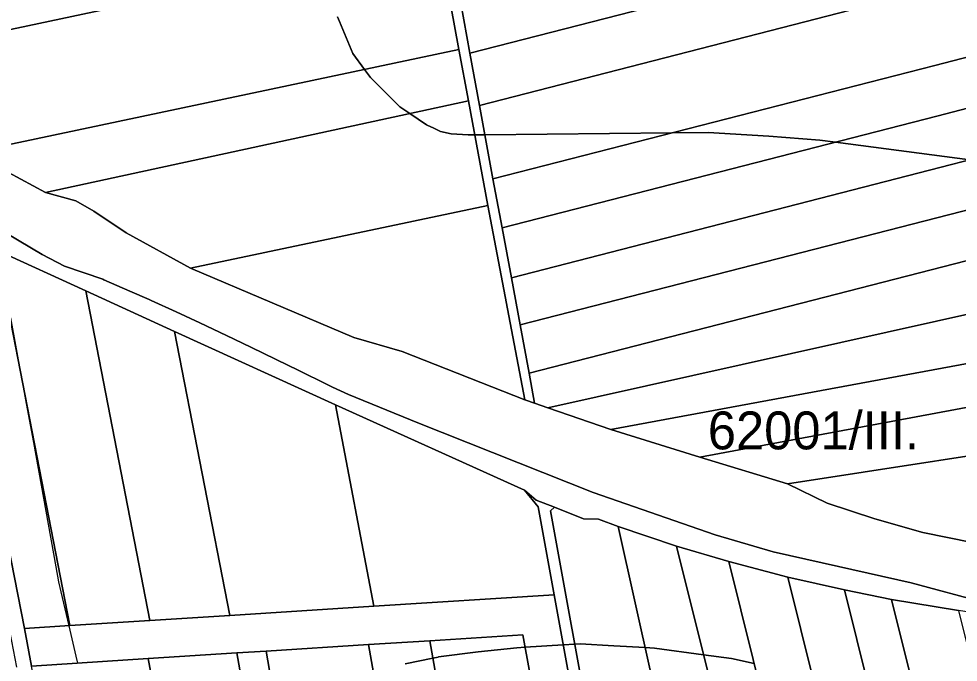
# Model space of a CAD drawing. Extents: x -521939 to -516426, y -1197857 to -1189551.
# Drawn here: x -519779.4 to -519407.3, y -1193004.4 to -1192749.7 of the extents above; entities that cross this region are included whole.
import ezdxf

# ---------------------------------------------------------------- set-up
doc = ezdxf.new("R2010")
doc.units = 0
for name, color, linetype in [('95560013', 7, 'Continuous'), ('95640013', 7, 'Continuous'), ('95660013', 7, 'Continuous')]:
    doc.layers.add(name, color=color, linetype=linetype)

msp = doc.modelspace()

# ---------------------------------------------------------------- linework, layer by layer
at = {"layer": '95560013'}
for points in [[(-519613.24, -1192717.85), (-519676.82, -1192731.35), (-519853.29, -1192768.82), (-519889.94, -1192741.9), (-519712.96, -1192704.38), (-519619.47, -1192684.56)], [(-519412.38, -1192694.25), (-519407.47, -1192713.71), (-519600.82, -1192763.32), (-519604.4, -1192743.51)], [(-519407.47, -1192713.71), (-519402.4, -1192733.96), (-519417.77, -1192737.92), (-519596.97, -1192784.09), (-519600.82, -1192763.32)], [(-519605.13, -1192761.84), (-519798.31, -1192802.61), (-519853.29, -1192768.82), (-519676.82, -1192731.35), (-519613.24, -1192717.85)], [(-519596.97, -1192784.09), (-519417.77, -1192737.92), (-519402.4, -1192733.96), (-519395.16, -1192762.71), (-519416.57, -1192768.19), (-519591.64, -1192813)], [(-519768.91, -1192818.48), (-519798.31, -1192802.61), (-519605.13, -1192761.84), (-519601.35, -1192782.23)], [(-519591.64, -1192813), (-519416.57, -1192768.19), (-519395.16, -1192762.71), (-519390.4, -1192781.7), (-519415.79, -1192788.23), (-519587.96, -1192832.51)], [(-519711.44, -1192848.38), (-519736.95, -1192834.43), (-519749.68, -1192825.91), (-519756.9, -1192821.72), (-519768.91, -1192818.48), (-519601.35, -1192782.23), (-519593.72, -1192823.59)], [(-519587.96, -1192832.51), (-519415.79, -1192788.23), (-519390.4, -1192781.7), (-519385.51, -1192801.11), (-519409.97, -1192807.4), (-519584.34, -1192852.24)], [(-519385.51, -1192801.11), (-519380.86, -1192819.59), (-519406.01, -1192826.04), (-519580.89, -1192870.89), (-519584.34, -1192852.24), (-519409.97, -1192807.4)], [(-519380.86, -1192819.59), (-519376.15, -1192838.32), (-519404.18, -1192845.51), (-519577.35, -1192889.93), (-519580.89, -1192870.89), (-519406.01, -1192826.04)], [(-519578.96, -1192900.47), (-519627.56, -1192881.34), (-519646.77, -1192875.82), (-519711.44, -1192848.38), (-519593.72, -1192823.59)], [(-519807.94, -1192834.96), (-519805.68, -1192833.36), (-519788.21, -1192841.3), (-519759.2, -1192989.89), (-519777.13, -1192991.04)], [(-519575.19, -1192901.81), (-519577.35, -1192889.93), (-519404.18, -1192845.51), (-519376.15, -1192838.32), (-519370.94, -1192859.31), (-519396.4, -1192864.98), (-519569.95, -1192903.63)], [(-519727.53, -1192987.89), (-519759.2, -1192989.89), (-519788.21, -1192841.3), (-519752.94, -1192857.37)], [(-519695.85, -1192985.85), (-519727.53, -1192987.89), (-519752.94, -1192857.37), (-519717.76, -1192873.41)], [(-519365.89, -1192879.09), (-519544.98, -1192912.28), (-519569.95, -1192903.63), (-519396.4, -1192864.98), (-519370.94, -1192859.31)], [(-519695.85, -1192985.85), (-519717.76, -1192873.41), (-519653.99, -1192902.46), (-519638.79, -1192982.16)], [(-519509.74, -1192923.15), (-519544.98, -1192912.28), (-519365.89, -1192879.09), (-519361.74, -1192895.7)], [(-519475.01, -1192933.77), (-519509.74, -1192923.15), (-519361.74, -1192895.7), (-519356.73, -1192915.59)], [(-519638.79, -1192982.16), (-519653.99, -1192902.46), (-519579.08, -1192936.23), (-519573.73, -1192942.87), (-519567.38, -1192977.66)], [(-519440.39, -1192947.55), (-519459.24, -1192941.4), (-519475.01, -1192933.77), (-519356.73, -1192915.59), (-519343.21, -1192969.49), (-519360.04, -1192967.68), (-519382.21, -1192963.28), (-519382, -1192962.28), (-519401.78, -1192957), (-519421.33, -1192953.08)], [(-519568.87, -1192944.42), (-519567.2, -1192943.06), (-519555.74, -1192947.57), (-519549.76, -1192947.78), (-519542.07, -1192950.61), (-519502.89, -1193125.92), (-519492.9, -1193170.62), (-519526.25, -1193178), (-519534.72, -1193131.58)], [(-519467.25, -1193165.07), (-519492.9, -1193170.62), (-519502.89, -1193125.92), (-519542.07, -1192950.61), (-519518.93, -1192958.37), (-519470.42, -1193152.39)], [(-519449.34, -1193161.11), (-519467.25, -1193165.07), (-519470.42, -1193152.39), (-519518.93, -1192958.37), (-519498.2, -1192964.55), (-519455.01, -1193138.3)], [(-519498.2, -1192964.55), (-519474.87, -1192970.68), (-519428.65, -1193156.57), (-519449.34, -1193161.11), (-519455.01, -1193138.3)], [(-519428.65, -1193156.57), (-519474.87, -1192970.68), (-519452.37, -1192975.76), (-519408.54, -1193152.16)], [(-519452.37, -1192975.76), (-519433.72, -1192979.51), (-519391.66, -1193148.43), (-519408.54, -1193152.16)], [(-519391.66, -1193148.43), (-519433.72, -1192979.51), (-519407.22, -1192983.93), (-519367.63, -1193143.15)], [(-519640.92, -1192997.38), (-519616.64, -1192995.84), (-519585.28, -1193173.27), (-519553.92, -1193350.7), (-519548.25, -1193382.78), (-519572.11, -1193387.02), (-519577.77, -1193354.97), (-519609.36, -1193176.09)], [(-519616.64, -1192995.84), (-519579.74, -1192993.48), (-519548.08, -1193166.93), (-519529.92, -1193266.42), (-519503.38, -1193374.77), (-519548.25, -1193382.78), (-519553.92, -1193350.7), (-519585.28, -1193173.27)], [(-519681.4, -1192999.94), (-519640.92, -1192997.38), (-519609.36, -1193176.09), (-519577.77, -1193354.97), (-519572.11, -1193387.02), (-519613.26, -1193394.37), (-519620.4, -1193353.04), (-519650.9, -1193176.49)], [(-519774.46, -1193005.9), (-519728.13, -1193002.94), (-519715.07, -1193073.69), (-519701.27, -1193154.26), (-519723.2, -1193155.82), (-519744.93, -1193157.32)], [(-519728.13, -1193002.94), (-519693.03, -1193000.71), (-519661.73, -1193177.89), (-519632.67, -1193342.39), (-519623.18, -1193396.11), (-519655.8, -1193401.93), (-519668.98, -1193330.14), (-519701.27, -1193154.26), (-519715.07, -1193073.69)], [(-519693.03, -1193000.71), (-519681.4, -1192999.94), (-519650.9, -1193176.49), (-519620.4, -1193353.04), (-519613.26, -1193394.37), (-519623.18, -1193396.11), (-519632.67, -1193342.39), (-519661.73, -1193177.89)]]:
    msp.add_lwpolyline(points, close=True, dxfattribs=at)
at = {"layer": '95640013'}
for points in [[(-519604.4, -1192743.51), (-519600.82, -1192763.32), (-519596.97, -1192784.09), (-519591.64, -1192813), (-519587.96, -1192832.51), (-519584.34, -1192852.24), (-519580.89, -1192870.89), (-519577.35, -1192889.93), (-519575.19, -1192901.81), (-519578.65, -1192900.59), (-519578.96, -1192900.47), (-519593.72, -1192823.59), (-519601.35, -1192782.23), (-519605.13, -1192761.84), (-519613.24, -1192717.85)], [(-519798.31, -1192802.61), (-519768.91, -1192818.48), (-519756.9, -1192821.72), (-519749.68, -1192825.91), (-519736.95, -1192834.43), (-519711.44, -1192848.38), (-519646.77, -1192875.82), (-519627.56, -1192881.34), (-519578.96, -1192900.47), (-519578.65, -1192900.59), (-519575.19, -1192901.81), (-519569.95, -1192903.63), (-519544.98, -1192912.28), (-519509.74, -1192923.15), (-519475.01, -1192933.77), (-519459.24, -1192941.4), (-519440.39, -1192947.55), (-519421.33, -1192953.08), (-519401.78, -1192957)], [(-519803.79, -1192823.02), (-519770.17, -1192843), (-519761.29, -1192847.68), (-519746.17, -1192852.82), (-519745.77, -1192853), (-519735.5, -1192857.45), (-519727.74, -1192860.81), (-519727.02, -1192861.14), (-519717.04, -1192865.69), (-519707.74, -1192869.98), (-519697.18, -1192875), (-519687.55, -1192879.63), (-519677.43, -1192884.57), (-519668.57, -1192888.89), (-519657.29, -1192894.4), (-519655.13, -1192895.45), (-519648.88, -1192898.4), (-519621.37, -1192909.57), (-519551.94, -1192937.22), (-519503.57, -1192953.95), (-519480.63, -1192960.73), (-519454.77, -1192966.51), (-519425.99, -1192972.98), (-519396.52, -1192980.8)], [(-519396.52, -1192980.8), (-519425.99, -1192972.98), (-519454.77, -1192966.51), (-519480.63, -1192960.73), (-519503.57, -1192953.95), (-519551.94, -1192937.22), (-519621.37, -1192909.57), (-519648.88, -1192898.4), (-519655.13, -1192895.45), (-519657.29, -1192894.4), (-519668.57, -1192888.89), (-519677.43, -1192884.57), (-519687.55, -1192879.63), (-519697.18, -1192875), (-519707.74, -1192869.98), (-519717.04, -1192865.69), (-519727.02, -1192861.14), (-519727.74, -1192860.81), (-519735.5, -1192857.45), (-519745.77, -1192853), (-519746.17, -1192852.82), (-519761.29, -1192847.68), (-519770.17, -1192843), (-519803.79, -1192823.02)], [(-519780.28, -1193006.26), (-519782.25, -1192996.08), (-519784.81, -1192982.88), (-519787.23, -1192970.27), (-519790.02, -1192955.94), (-519791.25, -1192949.89), (-519793.98, -1192935.35), (-519796.43, -1192922.84), (-519803.58, -1192886.35), (-519805.03, -1192878.79), (-519805.96, -1192874.02), (-519808.24, -1192862.04), (-519811.27, -1192846.68), (-519814.71, -1192832.73), (-519819.07, -1192827.26), (-519805.68, -1192833.36), (-519807.94, -1192834.96), (-519777.13, -1192991.04), (-519774.46, -1193005.9)], [(-519267.23, -1193005.51), (-519302.57, -1193000.06), (-519316.79, -1192997.86), (-519379.4, -1192988.21), (-519407.22, -1192983.93), (-519433.72, -1192979.51), (-519452.37, -1192975.76), (-519474.87, -1192970.68), (-519498.2, -1192964.55), (-519518.93, -1192958.37), (-519542.07, -1192950.61), (-519549.76, -1192947.78), (-519555.74, -1192947.57), (-519567.2, -1192943.06), (-519574.51, -1192940.18), (-519579.08, -1192936.23), (-519653.99, -1192902.46), (-519717.76, -1192873.41), (-519752.94, -1192857.37), (-519788.21, -1192841.3)], [(-519550.99, -1193067.69), (-519567.38, -1192977.66), (-519573.73, -1192942.87), (-519579.08, -1192936.23), (-519574.51, -1192940.18), (-519567.2, -1192943.06), (-519568.87, -1192944.42), (-519534.72, -1193131.58)], [(-519548.08, -1193166.93), (-519579.74, -1192993.48), (-519616.64, -1192995.84), (-519640.92, -1192997.38), (-519681.4, -1192999.94), (-519693.03, -1193000.71), (-519728.13, -1193002.94), (-519774.46, -1193005.9), (-519777.13, -1192991.04), (-519759.2, -1192989.89), (-519727.53, -1192987.89), (-519695.85, -1192985.85), (-519638.79, -1192982.16), (-519567.38, -1192977.66), (-519550.99, -1193067.69)]]:
    msp.add_lwpolyline(points, dxfattribs=at)
at = {"layer": '95660013'}
for points in [[(-519653.26, -1192748.94), (-519652.46, -1192750.83), (-519647.11, -1192763.43), (-519642.51, -1192769.73), (-519640.16, -1192772.94), (-519628.57, -1192784.53), (-519624.53, -1192787.25), (-519617.9, -1192791.71), (-519617.22, -1192792.03), (-519616.81, -1192792.22), (-519614.74, -1192793.16), (-519612.34, -1192794.26), (-519608.17, -1192795.19), (-519601.44, -1192795.65), (-519598.88, -1192795.63), (-519594.85, -1192795.59), (-519520.8, -1192794.87), (-519506.4, -1192794.73), (-519482.29, -1192796.12), (-519462.12, -1192797.74), (-519455.92, -1192798.55), (-519402.69, -1192805.53)], [(-519402.69, -1192805.53), (-519455.92, -1192798.55), (-519462.12, -1192797.74), (-519482.29, -1192796.12), (-519506.4, -1192794.73), (-519520.8, -1192794.87), (-519594.85, -1192795.59), (-519598.88, -1192795.63), (-519601.44, -1192795.65), (-519608.17, -1192795.19), (-519612.34, -1192794.26), (-519614.74, -1192793.16), (-519616.81, -1192792.22), (-519617.22, -1192792.03), (-519617.9, -1192791.71), (-519624.53, -1192787.25), (-519628.57, -1192784.53), (-519640.16, -1192772.94), (-519642.51, -1192769.73), (-519647.11, -1192763.43), (-519652.46, -1192750.83), (-519653.26, -1192748.94)], [(-519756.05, -1193004.72), (-519756.71, -1193001.91), (-519759.52, -1192989.91), (-519762.66, -1192976.53), (-519763.6, -1192972.52), (-519764.66, -1192966.64), (-519773.53, -1192917.46), (-519776.38, -1192901.91), (-519782.57, -1192868.08)], [(-519756.05, -1193004.72), (-519756.71, -1193001.91), (-519759.52, -1192989.91), (-519762.66, -1192976.53), (-519763.6, -1192972.52), (-519764.66, -1192966.64), (-519773.53, -1192917.46), (-519776.38, -1192901.91), (-519782.57, -1192868.08)], [(-519488.17, -1193004.9), (-519497.08, -1193002.92), (-519508.17, -1193001.41), (-519527.68, -1192998.75), (-519531.36, -1192998.55), (-519543.79, -1192997.86), (-519557.12, -1192997.12), (-519559.23, -1192997.25), (-519563.76, -1192997.52), (-519578.84, -1192998.43), (-519582.16, -1192998.63), (-519597.46, -1193000.19), (-519613.22, -1193002.28), (-519613.3, -1193002.3), (-519615.42, -1193002.74), (-519626.44, -1193005)], [(-519626.44, -1193005), (-519615.42, -1193002.74), (-519613.3, -1193002.3), (-519613.22, -1193002.28), (-519597.46, -1193000.19), (-519582.16, -1192998.63), (-519578.84, -1192998.43), (-519563.76, -1192997.52), (-519559.23, -1192997.25), (-519557.12, -1192997.12), (-519543.79, -1192997.86), (-519531.36, -1192998.55), (-519527.68, -1192998.75), (-519508.17, -1193001.41), (-519497.08, -1193002.92), (-519488.17, -1193004.9)]]:
    msp.add_lwpolyline(points, dxfattribs=at)

# ---------------------------------------------------------------- texts
msp.add_text('62001/III.', height=15, rotation=360, dxfattribs=at).set_placement((-519506.52, -1192920.12))

doc.saveas('drawing.dxf')
